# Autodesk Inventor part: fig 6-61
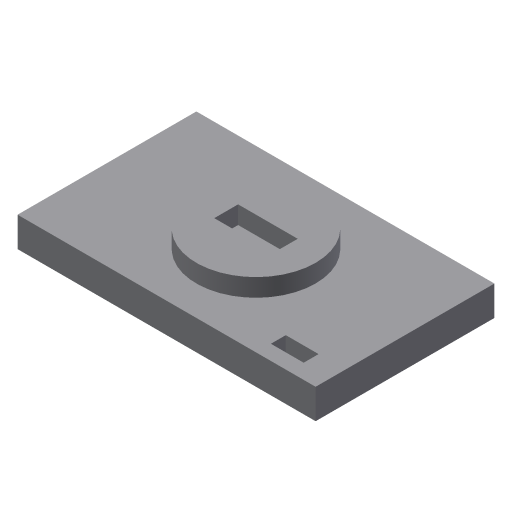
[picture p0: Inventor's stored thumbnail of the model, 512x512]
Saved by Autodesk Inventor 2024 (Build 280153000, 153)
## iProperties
Created: 2007-01
Part Number: fig 6-61
Document SubType Name: Modeling
Designer: Administrator
Density: 1 g/cm^3
Material: Generic
Appearance: Default
Author: Administrator
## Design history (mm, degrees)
sketch "Sketch1"
  geometry: L1 (-50, 30)-(50, 30); L2 (50, 30)-(50, -30); L3 (50, -30)-(-50, -30); L4 (-50, -30)-(-50, 30); 1 further point
  constraints: 8 end point, 2 parallel, 1 horizontal, 1 perpendicular, 1 other
  dimensions: "d0" = 50 distance from line of L4 point (0, 0); "d1" = 100 distance of L1.start L1.end; "d2" = 30 distance from line of L3 point (0, 0); "d3" = 60 distance between parallel lines of L3 L1
extrude "Extrusion1" new body sketch "Sketch1" distance "d4" = 10; taper "d5" = 0 deg
sketch "Sketch2"
  geometry: L1 (10, -4)-(-10, -4); L2 (-10, -4)-(-10, 4); L3 (-10, 4)-(10, 4); L4 (10, 4)-(10, -4); C1 r 20 at (0, 0); 1 further point
  constraints: 8 end point, 2 parallel, 1 centre point, 1 coincident, 1 horizontal, 1 perpendicular, 1 other
  dimensions: "d6" = 40 diameter of C1; "d7" = 4 distance from line of L3 point (0, 0); "d8" = 8 distance between parallel lines of L1 L3; "d9" = 10 distance from line of L2 point (0, 0); "d10" = 20 distance between parallel lines of L4 L2
extrude "Extrusion2" join sketch "Sketch2" distance "d11" = 6; taper "d12" = 0 deg
sketch "Sketch3"
  geometry: L1 (30, -20)-(41, -20); L2 (41, -20)-(41, -25); L3 (41, -25)-(30, -25); L4 (30, -25)-(30, -20)
  constraints: 8 end point, 2 parallel, 1 horizontal, 1 perpendicular
extrude "Extrusion3" cut sketch "Sketch3" extent not by distance; stored distance "d13" = 10; taper "d14" = 0 deg
body "Solid1"
